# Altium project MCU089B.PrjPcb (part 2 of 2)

## Sheet MCU089B_XDS110_USB_Power.SchDoc
size 431 x 279 mm; Date: Not shown in title block; ApprovedBy: Not shown in title block; CheckedBy: Not shown in title block; Author: Not shown in title block; CompanyName: Not shown in title block; Engineer: Not shown in title block; Organization: Not shown in title block; Address1: Not shown in title block; Address2: Not shown in title block; Address3: Not shown in title block; Address4: Not shown in title block; DocumentNumber: 6; Revision: Use project parameter SCH_Rev; SheetNumber: 6; SheetTotal: 8; PageSetup: Record=PageOptions¦CenterHorizontal=True¦CenterVertical=True¦PrintScale=1.00¦XCorrection=1.00¦YCorrection=1.00¦PrintKind=0¦BorderSize=5000000¦LeftOffset=0¦BottomOffset=0¦Orientation=2¦PaperLength=1000¦PaperWidth=1000¦Scale=100¦PaperSource=15¦PrintQuality=600¦MediaType=1¦DitherType=10¦PaperKind=Letter¦PrintScaleMode=1
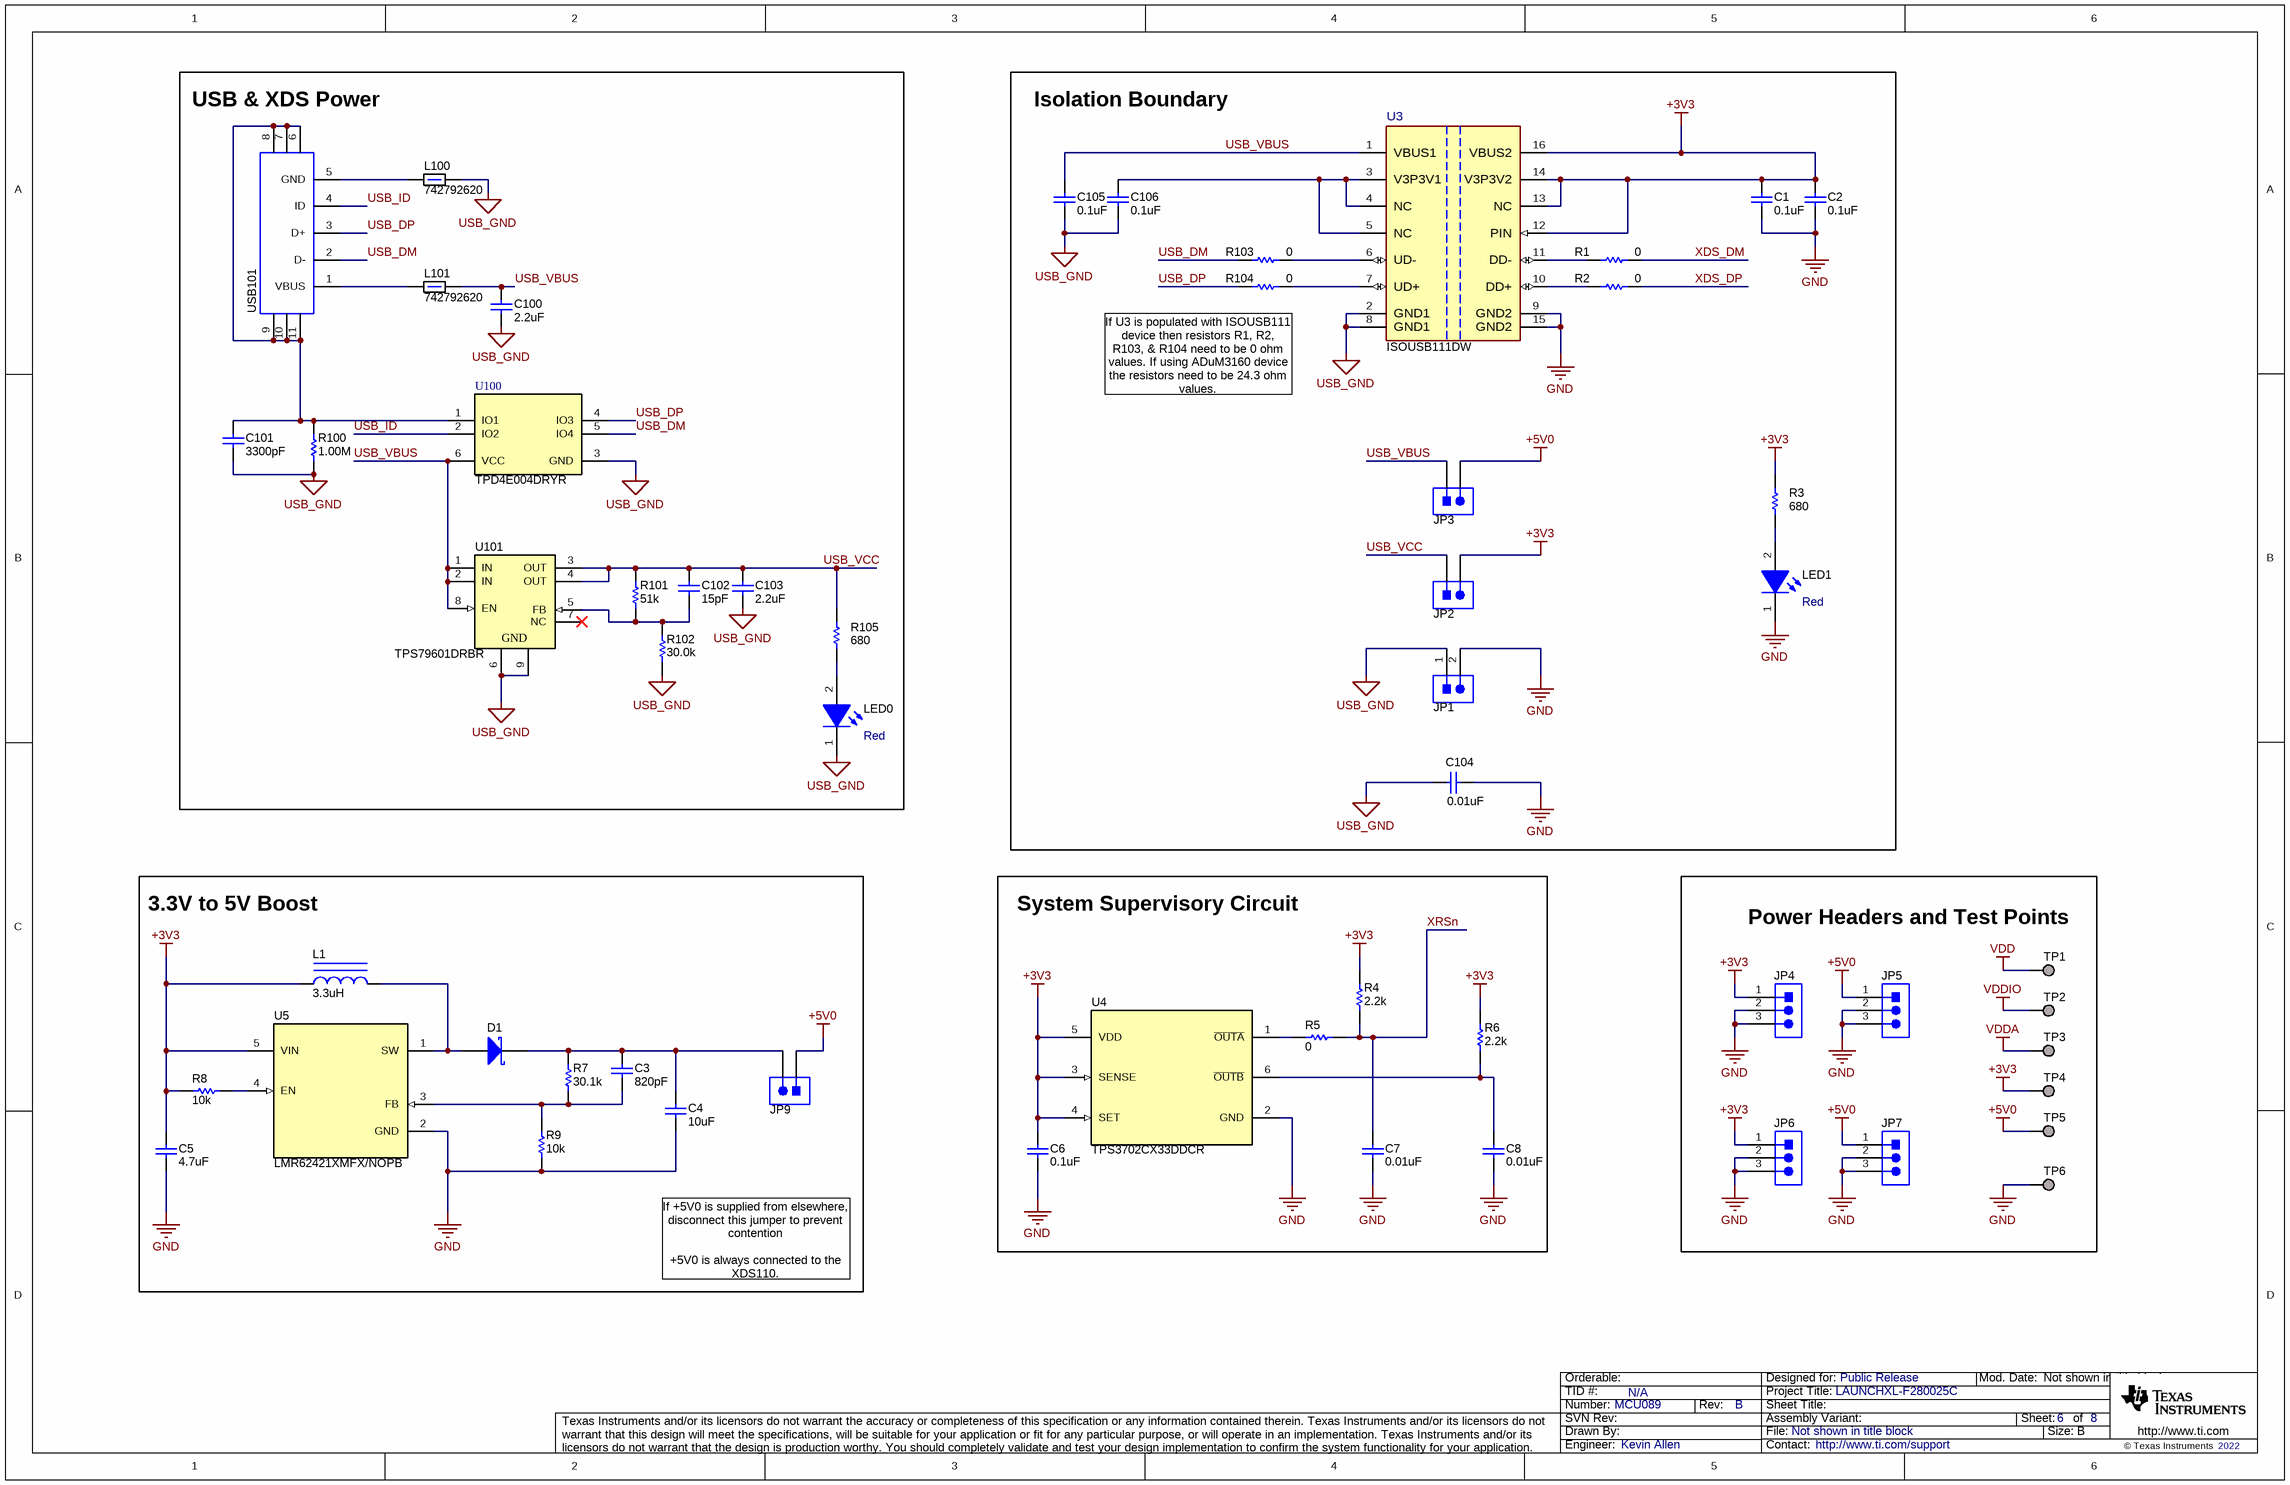
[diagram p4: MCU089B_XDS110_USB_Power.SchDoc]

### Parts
C1  ValueDisplayed: 0.1uF  [0402]  (hidden comment: GRM155R71A104KA01D)
C2  ValueDisplayed: 0.1uF  [0402]  (hidden comment: GRM155R71A104KA01D)
C3  ValueDisplayed: 820pF  [0402]  (hidden comment: GRM1555C1E821JA01D)
C4  ValueDisplayed: 10uF  [1210_220]  (hidden comment: 885012209028)
C5  ValueDisplayed: 4.7uF  [0402]  (hidden comment: 885012105008)
C6  ValueDisplayed: 0.1uF  [0402]  (hidden comment: GRM155R71A104KA01D)
C7  ValueDisplayed: 0.01uF  [0402]  (hidden comment: GRM155R71E103KA01D)
C8  ValueDisplayed: 0.01uF  [0402]  (hidden comment: GRM155R71E103KA01D)
C100  ValueDisplayed: 2.2uF  [0402]  (hidden comment: GRM155R60J225KE95D)
C101  ValueDisplayed: 3300pF  [0402]  (hidden comment: GRM155R71H332KA01D)
C102  ValueDisplayed: 15pF  [0402]  (hidden comment: 885012005056)
C103  ValueDisplayed: 2.2uF  [0402]  (hidden comment: GRM155R60J225KE95D)
C104  ValueDisplayed: 0.01uF  [1812]  (hidden comment: 1812SC103KAT1A)
C105  ValueDisplayed: 0.1uF  [0402]  (hidden comment: GRM155R71A104KA01D)
C106  ValueDisplayed: 0.1uF  [0402]  (hidden comment: GRM155R71A104KA01D)
D1  1N5819HW-7-F  [SOD-123]  (value not drawn)
JP1  61300211121  [WURTH_61300211121]  (value not drawn)
JP2  61300211121  [WURTH_61300211121]  (value not drawn)
JP3  61300211121  [WURTH_61300211121]  (value not drawn)
JP4  61300311121  [WURTH_61300311121]  (value not drawn)
JP5  61300311121  [WURTH_61300311121]  (value not drawn)
JP6  61300311121  [WURTH_61300311121]  (value not drawn)
JP7  61300311121  [WURTH_61300311121]  (value not drawn)
JP9  61300211121  [WURTH_61300211121]  (value not drawn)
L1  ValueDisplayed: 3.3uH  [WE-TPC_2828]  (hidden comment: 744025003)
L100  742792620  [0603]
L101  742792620  [0603]
LED0  value Red  [WL-SMCW_RED_0805]  (hidden comment: 150080SS75000)
LED1  value Red  [WL-SMCW_RED_0805]  (hidden comment: 150080SS75000)
R1  ValueDisplayed: 0  [0402]  (hidden comment: RC0402JR-070RL)
R2  ValueDisplayed: 0  [0402]  (hidden comment: RC0402JR-070RL)
R3  ValueDisplayed: 680  [0402]  (hidden comment: CRCW0402680RJNED)
R4  ValueDisplayed: 2.2k  [0402]  (hidden comment: CRCW04022K20JNED)
R5  ValueDisplayed: 0  [0402]  (hidden comment: CRCW04020000Z0ED)
R6  ValueDisplayed: 2.2k  [0603]  (hidden comment: CRCW06032K20JNEA)
R7  ValueDisplayed: 30.1k  [0402]  (hidden comment: RC0402FR-0730K1L)
R8  ValueDisplayed: 10k  [0402]  (hidden comment: CRCW040210K0JNED)
R9  ValueDisplayed: 10k  [0402]  (hidden comment: CRCW040210K0JNED)
R100  ValueDisplayed: 1.00M  [0402]  (hidden comment: CRCW04021M00FKED)
R101  ValueDisplayed: 51k  [0402]  (hidden comment: CRCW040251K0FKED)
R102  ValueDisplayed: 30.0k  [0402]  (hidden comment: CRCW040230K0FKED)
R103  ValueDisplayed: 0  [0402]  (hidden comment: RC0402JR-070RL)
R104  ValueDisplayed: 0  [0402]  (hidden comment: RC0402JR-070RL)
R105  ValueDisplayed: 680  [0402]  (hidden comment: CRCW0402680RJNED)
TP1  TESTPOINT  [TP_50MIL-25MILHOLE]  (value not drawn)  (no BOM)
TP2  TESTPOINT  [TP_50MIL-25MILHOLE]  (value not drawn)  (no BOM)
TP3  TESTPOINT  [TP_50MIL-25MILHOLE]  (value not drawn)  (no BOM)
TP4  TESTPOINT  [TP_50MIL-25MILHOLE]  (value not drawn)  (no BOM)
TP5  TESTPOINT  [TP_50MIL-25MILHOLE]  (value not drawn)  (no BOM)
TP6  TESTPOINT  [TP_50MIL-25MILHOLE]  (value not drawn)  (no BOM)
U3  ISOUSB111DW  [DW0016B-MFG]
U4  TPS3702CX33DDCR  [DDC0006A_N]
U5  LMR62421XMFX/NOPB  [DBV0005A_N]
U100  TPD4E004DRYR  [DRY0006A]
U101  TPS79601DRBR  [DRB0008B]
USB101  1051640001  [Molex_1051640001]  (value not drawn)

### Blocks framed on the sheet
USB & XDS Power: C100-C103 L100 L101 LED0 R100-R102 R105 U100 U101 USB101
Isolation Boundary: C1 C2 C104-C106 JP1-JP3 LED1 R1-R3 R103 R104 U3
3.3V to 5V Boost: C3-C5 D1 JP9 L1 R7-R9 U5
System Supervisory Circuit: C6-C8 R4-R6 U4
Power Headers and Test Points: JP4-JP7 TP1-TP6

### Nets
+3V3: C1.2 C2.2 C5.1 C6.2 JP2.2 JP4.1 JP6.1 L1.1 R3.2 R4.2 R6.2 R8.2 TP4.1 U3.12(PIN) U3.13(NC) U3.14(V3P3V2) U3.16(VBUS2) U4.3(SENSE) U4.4(SET) U4.5(VDD) U5.5(VIN)
+5V0: JP3.2 JP5.1 JP7.1 JP9.1 TP5.1
GND: C1.1 C2.1 C4.2 C5.2 C6.1 C7.2 C8.2 C104.1 JP1.2 JP4.2 JP4.3 JP5.2 JP5.3 JP6.2 JP6.3 JP7.2 JP7.3 LED1.1(K) R9.1 TP6.1 U3.9(GND2) U3.15(GND2) U4.2(GND) U5.2(GND)
USB_GND: C100.2 C101.2 C103.2 C104.2 C105.1 C106.1 JP1.1 L100.2 LED0.1(K) R100.1 R102.1 U3.2(GND1) U3.8(GND1) U100.3(GND) U101.6(GND) U101.9(GND)
VDD: TP1.1
VDDA: TP3.1
VDDIO: TP2.1
USB_DM: R103.1 U100.5(IO4) USB101.2(D-)
USB_DP: R104.1 U100.4(IO3) USB101.3(D+)
USB_ID: U100.2(IO2) USB101.4(ID)
USB_VBUS: C100.1 C105.2 JP3.1 L101.2 U3.1(VBUS1) U100.6(VCC) U101.1(IN) U101.2(IN) U101.8(EN)
USB_VCC: C102.1 C103.1 JP2.1 R101.2 R105.2 U101.3(OUT) U101.4(OUT)
XDS_DM: R1.2
XDS_DP: R2.2
XRSn: C7.1 R4.1 R5.2
NetC3_1: C3.1 C4.1 D1.1(K) JP9.2 R7.2
NetC3_2: C3.2 R7.1 R9.2 U5.3(FB)
NetC8_1: C8.1 R6.1 U4.6(~{OUTB})
NetC101_1: C101.1 R100.2 U100.1(IO1) USB101.6 USB101.7 USB101.8 USB101.9 USB101.10 USB101.11
NetC102_2: C102.2 R101.1 R102.2 U101.5(FB)
NetC106_2: C106.2 U3.3(V3P3V1) U3.4(NC) U3.5(NC)
NetD1_2: D1.2(A) L1.2 U5.1(SW)
NetL100_1: L100.1 USB101.5(GND)
NetL101_1: L101.1 USB101.1(VBUS)
NetLED0_2: LED0.2(A) R105.1
NetLED1_2: LED1.2(A) R3.1
NetR1_1: R1.1 U3.11(DD-)
NetR2_1: R2.1 U3.10(DD+)
NetR5_1: R5.1 U4.1(~{OUTA})
NetR8_1: R8.1 U5.4(EN)
NetR103_2: R103.2 U3.6(UD-)
NetR104_2: R104.2 U3.7(UD+)

Not connected (* = marked no-connect by the designer): U101 7(NC)*

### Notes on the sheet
- (near R104) If U3 is populated with ISOUSB111 device then resistors R1, R2, R103, & R104 need to be 0 ohm values. If using ADuM3160 device the resistors need to be 24.3 ohm values.
- If +5V0 is supplied from elsewhere, disconnect this jumper to prevent contention
  +5V0 is always connected to the XDS110.

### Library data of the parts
C1 C2 C6 C105 C106 = CMP-0006629-2: CAP, CERM, 0.1 uF, 10 V, +/- 10%, X7R, 0402; Manufacturer: MuRata; Polarized: N; Value: 0.1uF; U/M: EA; Cap_F: 100nF; Value1: Unknown; VDC_V: 10V; TaMin_C: -55°C; TaMax_C: 125°C; SizeArea_mm2: 0.5; SizeAreaWB_mm2: 3; SizeX_mm: 1; SizeZ_mm: 0.6; AEC Category: Q200
C3 = CMP-0006404-2: CAP, CERM, 820 pF, 25 V, +/- 5%, C0G/NP0, 0402; Manufacturer: MuRata; TaMin_C: -55°C; Polarized: N; SizeAreaWB_mm2: 3; Value1: Unknown; U/M: EA; Value: 820pF; TaMax_C: 125°C; SizeZ_mm: 0.6; SizeX_mm: 1; SizeY_mm: 0.5; Value2: 25V; AEC Category: Q200
C4 = CMP-0064938-2: CAP, CERM, 10 uF, 25 V,+/- 10%, X7R, 1210; Manufacturer: Wurth Elektronik; Polarized: N; Value: 10uF; U/M: EA; Cap_F: 10µF; Value1: Unknown; VDC_V: 25V; TaMin_C: -55°C; TaMax_C: 125°C; Cap_Case: 1210; SizeArea_mm2: 8; SizeAreaWB_mm2: 14.7; SizeX_mm: 3.2; SizeY_mm: 2.5; SizeZ_mm: 2.2; AEC Category: Q200
C5 = CMP-0006220-2: CAP, CERM, 4.7 uF, 6.3 V, +/- 20%, X5R, 0402; Manufacturer: Wurth Elektronik; Polarized: N; Value: 4.7uF; U/M: EA; Cap_F: 4.7µF; Value1: Unknown; VDC_V: 6.3V; TaMin_C: -55°C; TaMax_C: 85°C; SizeArea_mm2: 0.5; SizeAreaWB_mm2: 3; SizeX_mm: 1; SizeZ_mm: 0.6; AEC Category: Q200
C7 C8 = CMP-0006658-2: CAP, CERM, 0.01 uF, 25 V, +/- 10%, X7R, 0402; Manufacturer: MuRata; Polarized: N; Value: 0.01uF; U/M: EA; Cap_F: 10nF; Value1: Unknown; VDC_V: 25V; TaMin_C: -55°C; TaMax_C: 125°C; SizeArea_mm2: 0.5; SizeAreaWB_mm2: 3; SizeX_mm: 1; SizeZ_mm: 0.6; AEC Category: Q200
C100 C103 = CMP-0006543-2: CAP, CERM, 2.2 uF, 6.3 V, +/- 10%, X5R, 0402; Manufacturer: MuRata; Polarized: N; Value: 2.2uF; U/M: EA; Cap_F: 2.2µF; Value1: Unknown; VDC_V: 6.3V; TaMin_C: -55°C; TaMax_C: 85°C; SizeArea_mm2: 0.5; SizeAreaWB_mm2: 3; SizeX_mm: 1; SizeZ_mm: 0.6; AEC Category: Q200
C101 = CMP-0006688-2: CAP, CERM, 3300 pF, 50 V, +/- 10%, X7R, 0402; Manufacturer: MuRata; Polarized: N; Value: 3300pF; U/M: EA; Cap_F: 3.3nF; Value1: Unknown; VDC_V: 50V; TaMin_C: -55°C; TaMax_C: 125°C; SizeArea_mm2: 0.5; SizeAreaWB_mm2: 3; SizeX_mm: 1; SizeZ_mm: 0.6; AEC Category: Q200
C102 = CMP-0006216-2: CAP, CERM, 15 pF, 50 V, +/- 5%, C0G/NP0, 0402; Manufacturer: Wurth Elektronik; Polarized: N; Value: 15pF; U/M: EA; Value1: Unknown; VDC_V: 50V; TaMin_C: -55°C; TaMax_C: 125°C; SizeArea_mm2: 0.5; SizeAreaWB_mm2: 3; SizeX_mm: 1; SizeZ_mm: 0.6; AEC Category: Q200
C104 = CMP-0009297-2: CAP, CERM, 0.01 uF, 1500 V, +/- 10%, X7R, 1812; Manufacturer: AVX; TaMin_C: -55°C; ESR_ohm: 0.05; Polarized: N; SizeAreaWB_mm2: 23.1; Value1: 0.05 ohm; U/M: EA; Value: 0.01uF; TaMax_C: 125°C; SizeZ_mm: 1.35; SizeX_mm: 4.5; SizeY_mm: 3.2; Value2: 1500V; SizeArea_mm2: 14.4; Cap_F: 10nF; VDC_V: 1.5kV; AEC Category: Q200
D1 = CMP-0028360-2: Diode, Schottky, 40 V, 1 A, SOD-123; Manufacturer: Diodes Inc.; Vf_V: 450mV; Value: 40V; Value1: 1A; Value2: 0.45V; TJmax_C: 125°C; SizeAreaWB_mm2: 13.095; SizeArea_mm2: 6.545; SizeX_mm: 3.85; SizeY_mm: 1.7; SizeZ_mm: 1.35; AEC Category: Q101; Green_Lifecycle: Active; Green_REACh: Passed
JP1-JP3 JP9 = CMP-0054794-1: Header, 2.54 mm, 2x1, Gold, TH; Manufacturer: Wurth Elektronik; Green_Lifecycle: Active; Green_REACh: Passed; CNHeader: TRUE; CT: FALSE
JP4-JP7 = CMP-0054796-1: Header, 2.54 mm, 3x1, Gold, TH; Manufacturer: Wurth Elektronik; Green_Lifecycle: Active; Green_REACh: Passed; CNHeader: TRUE; CT: FALSE
L1 = CMP-0063754-1: Inductor, Shielded Drum Core, Ferrite, 3.3 uH, 1.5 A, 0.085 ohm, SMD; Manufacturer: Wurth Elektronik; Value: 3.3uH; Ind_H: 3.3µH; Imax_A: 1.5A; Irms: 1.5A @ 40C rise; Isat: 1.8A @ 35% inductance drop; DCR_ohm: 0.085; SizeAreaWB_mm2: 14.44; SizeArea_mm2: 7.84; SizeX_mm: 2.8; SizeZ_mm: 3; AEC Category: Q200; Green_Lifecycle: Active; Green_REACh: Passed
L100 L101 = CMP-0003183-2: Ferrite Bead, 100 ohm @ 100 MHz, 0.5 A, 0603; Manufacturer: Wurth Elektronik; Ztyp@1GHz_Ohm: 137.267; ZTyp@100MHz_Ohm: 100; SizeAreaWB_mm2: 4.68; DCR_ohm: 1.5d; Value1: 0.15 ohm; Value: 100 ohm; Imax_A: 5dA; SizeZ_mm: 1; SizeX_mm: 1.6; SizeY_mm: 0.8; Value2: 0.5A; SizeArea_mm2: 1.28
LED0 LED1 = CMP-0002951-3: LED, Red, SMD; Manufacturer: Wurth Elektronik; Type: AlInGaP; Vf_V: 1.9V; Io_A: 30mA; Vr_V: 5V; Ir_A: 25µA; Tjmax_C: 85°C; Power_TotalModule: 72mW; Value1: 0.072W; Angle: 140
R1 R2 R103 R104 = CMP-0027004-2: RES, 0, 5%, 0.063 W, 0402; Manufacturer: Yageo America; Power_W: 63mW; TempCo: 200 ppm/C; Value_Code: 0000; U/M: EA; Value: 0; EIA_Code: E24; SizeX_mm: 1; SizeY_mm: 0.5; SizeZ_mm: 0.6; Value2: 0.063W; VDC_V: 50V; AEC Category: Q200
R3 R105 = CMP-0026962-3: RES, 680, 5%, 0.063 W, AEC-Q200 Grade 0, 0402; Manufacturer: Vishay-Dale; Power_W: 63mW; TempCo: 200 ppm/C; Value_Code: 680R; Value: 680; EIA_Code: E24; SizeX_mm: 1; SizeY_mm: 0.5; SizeZ_mm: 0.6; Value2: 0.063W; CompType: Resistor; AEC Qualified: Y; VDC_V: 50V; AEC Category: Q200; AEC Grade: 0
R4 = CMP-0026890-5: RES, 2.2 k, 5%, 0.063 W, AEC-Q200 Grade 0, 0402; Manufacturer: Vishay-Dale; Value: 2.2k; Value_Code: 2k20; Power_W: 63mW; Value2: 0.063W; VDC_V: 50V; TempCo: 200 ppm/C; SizeArea_mm2: 0.5; SizeX_mm: 1; SizeZ_mm: 0.6; EIA_Code: E24; AEC Category: Q200; AEC Qualified: Y; AEC Grade: 0
R5 = CMP-0026822-3: RES, 0, 5%, 0.063 W, AEC-Q200 Grade 0, 0402; Manufacturer: Vishay-Dale; Value: 0; Value_Code: 0000; Power_W: 63mW; Value2: 0.063W; VDC_V: 50V; TempCo: 200 ppm/C; SizeArea_mm2: 0.5; SizeX_mm: 1; SizeZ_mm: 0.6; EIA_Code: E24; AEC Category: Q200; AEC Qualified: Y
R6 = CMP-0025769-4: RES, 2.2 k, 5%, 0.1 W, AEC-Q200 Grade 0, 0603; Manufacturer: Vishay-Dale; Value: 2.2k; Value_Code: 2k20; Power_W: 100mW; Value2: 0.1W; VDC_V: 75V; TempCo: 200 ppm/C; SizeArea_mm2: 1.28; SizeX_mm: 1.6; SizeY_mm: 0.8; SizeZ_mm: 1; EIA_Code: E24; AEC Category: Q200; AEC Qualified: Y; AEC Grade: 0
R7 = CMP-0026730-1: RES, 30.1 k, 1%, 0.063 W, 0402; Manufacturer: Yageo America; Value: 30.1k; Value_Code: 30k1; Power_W: 63mW; Value2: 0.063W; VDC_V: 50V; TempCo: 100 ppm/C; SizeArea_mm2: 0.5; SizeX_mm: 1; SizeZ_mm: 0.6; EIA_Code: E96; U/M: EA; AEC Category: Q200; AEC Qualified: N
R8 R9 = CMP-0026825-5: RES, 10 k, 5%, 0.063 W, AEC-Q200 Grade 0, 0402; Manufacturer: Vishay-Dale; Value: 10k; Value_Code: 10k0; Power_W: 63mW; Value2: 0.063W; VDC_V: 50V; TempCo: 200 ppm/C; SizeArea_mm2: 0.5; SizeX_mm: 1; SizeZ_mm: 0.6; EIA_Code: E24; AEC Category: Q200; AEC Qualified: Y; AEC Grade: 0
R100 = CMP-0026100-2: RES, 1.00 M, 1%, 0.063 W, AEC-Q200 Grade 0, 0402; Manufacturer: Vishay-Dale; Value: 1.00Meg; Res_ohm: 1M; Value_Code: 1M00; Power_W: 63mW; Value2: 0.063W; VDC_V: 50V; TempCo: 100 ppm/C; SizeArea_mm2: 0.5; SizeX_mm: 1; SizeZ_mm: 0.6; EIA_Code: E96; AEC Category: Q200; AEC Qualified: Y; AEC Grade: 0
R101 = CMP-0088102-2: RES Thick Film SMD 51kΩ 1% 1/16W 0402 100ppm/K; Manufacturer: Vishay; SizeX_mm: 1; Power_W: 63mW; AEC Qualified: Yes; VDC_V: 50V; SizeZ_mm: 0.6; SizeY_mm: 0.5; AEC Grade: Grade 0
R102 = CMP-0078244-2: RES, 30.0 k, 1%, 0.063 W, AEC-Q200 Grade 0, 0402; Manufacturer: Vishay-Dale; Power_W: 63mW; Green_Lifecycle: Active; TempCo: 100 ppm/C; Value_Code: 30k0; Green_REACh: Passed; Value: 30.0k; Res_ohm: 30k; SizeX_mm: 1; SizeY_mm: 0.5; SizeZ_mm: 0.6; Value2: 0.063W; AEC Qualified: Y; VDC_V: 50V; AEC Grade: 0; AEC Category: Q200
TP1-TP6 = CMP-0078143-3: TEST POINT.  No entry in BOM.
U3 = CMP-0091303-1: Full/Low Speed Isolated USB Repeater, SOIC16-Wide; Manufacturer: Texas Instruments; Number Of Ports: 1; Usb Standard: USB 2.0; Min Supply Voltage: 3V; Data Rate: 12Mbits/s; Max Supply Voltage: 5.5V; TaMin_C: -40°C; SizeZ_mm: 2.65mm; TaMax_C: +125°C; Nominal Supply Current: 9-9.5mA; TJmax_C: +150°C; Standoff Height: 0.1mm; AEC Qualified: No
U4 = CMP-0067340-2: High-Accuracy, Fixed-Threshold OV/UV Monitor, DDC0006A (SOT-23-T-6); Alternate PartNumber: TPS3702CX33DDCT; Manufacturer: Texas Instruments; SizeArea_mm2: 4.8675; SizeAreaWB_mm2: 10.4675; SizeX_mm: 1.65; SizeY_mm: 2.95; SizeZ_mm: 0.87; CompType: IC; U/M: EA
U5 = CMP-0066119-1: SIMPLE SWITCHER 2.7V to 5.5V, 2.1A Step-Up Regulator in SOT-23, DBV0005A (SOT-23-5); Alternate PartNumber: LMR62421XMFE/NOPB; Manufacturer: Texas Instruments; SizeArea_mm2: 8.12; SizeAreaWB_mm2: 14.82; SizeX_mm: 2.8; SizeY_mm: 2.9; SizeZ_mm: 1.45; CompType: IC; U/M: EA; Green_Lifecycle: Active; Green_REACh: Passed
U100 = CMP-0043115-3: 4-Channel ESD Protection Array for High-Speed Data Interfaces, DRY0006A (USON-6); Manufacturer: Texas Instruments; 1394 / Firewire: TRUE; Breakdown Voltage(Min)(V): 6; Eco-Plan: Green (RoHS & no Sb/Br); IEC 61000-4-2 Air-Gap(+/- kV): 12; IEC 61000-4-2 Contact(+/- kV): 8; IO Capacitance(Typ)(pF): 1.6; IO Leakage Current(nA): 1; AEC Category: Q200; AEC Qualified: N; CompType: IC; SizeArea_mm2: 1.45; SizeAreaWB_mm2: 4.9; SizeX_mm: 1.0; SizeZ_mm: 0.6; Rating: Catalog
U101 = CMP-0036402-3: Single Output High PSRR LDO, 1 A, Adjustable 1.2 to 5.5 V Output, 2.7 to 5.5 V Input, 8-pin SON (DRB), -40 to 125 degC, Green (RoHS & no Sb/Br); Manufacturer: Texas Instruments; Accuracy(%): 2; Iout(Max)(A): 1; Iq(Typ)(mA): 0.26; SubFamily: Single Channel LDO; Vdo(Typ)(mV): 250; Vin(Max)(V): 5.5; Vin(Min)(V): 2.7; Vout Adj(Min)(V): 1.2; AEC Category: Q200; AEC Qualified: N; CompType: IC; SizeAreaWB_mm2: 16.0; SizeArea_mm2: 9.0; SizeX_mm: 3.0; SizeZ_mm: 1.0
USB101 = CMP-0055311-1: Receptacle, USB 2.0, Micro B, 5 Position, R/A, SMT; Manufacturer: Molex; Pitch_mm: 0.65; Gender: Female; ContactFinish: Gold; Current_A: 1.8A; Voltage_V: 30V; Cert_UL: Y; CNHeader: FALSE; CT: TRUE

## Sheet MCU089B_XDS110_MCU.SchDoc
size 431 x 279 mm; Date: Not shown in title block; ApprovedBy: Not shown in title block; CheckedBy: Not shown in title block; Author: Not shown in title block; CompanyName: Not shown in title block; Engineer: Not shown in title block; Organization: Not shown in title block; Address1: Not shown in title block; Address2: Not shown in title block; Address3: Not shown in title block; Address4: Not shown in title block; DocumentNumber: 7; Revision: Use project parameter SCH_Rev; SheetNumber: 7; SheetTotal: 8; PageSetup: Record=PageOptions¦CenterHorizontal=True¦CenterVertical=True¦PrintScale=1.00¦XCorrection=1.00¦YCorrection=1.00¦PrintKind=0¦BorderSize=5000000¦LeftOffset=0¦BottomOffset=0¦Orientation=2¦PaperLength=1000¦PaperWidth=1000¦Scale=100¦PaperSource=15¦PrintQuality=600¦MediaType=1¦DitherType=10¦PaperKind=Letter¦PrintScaleMode=1
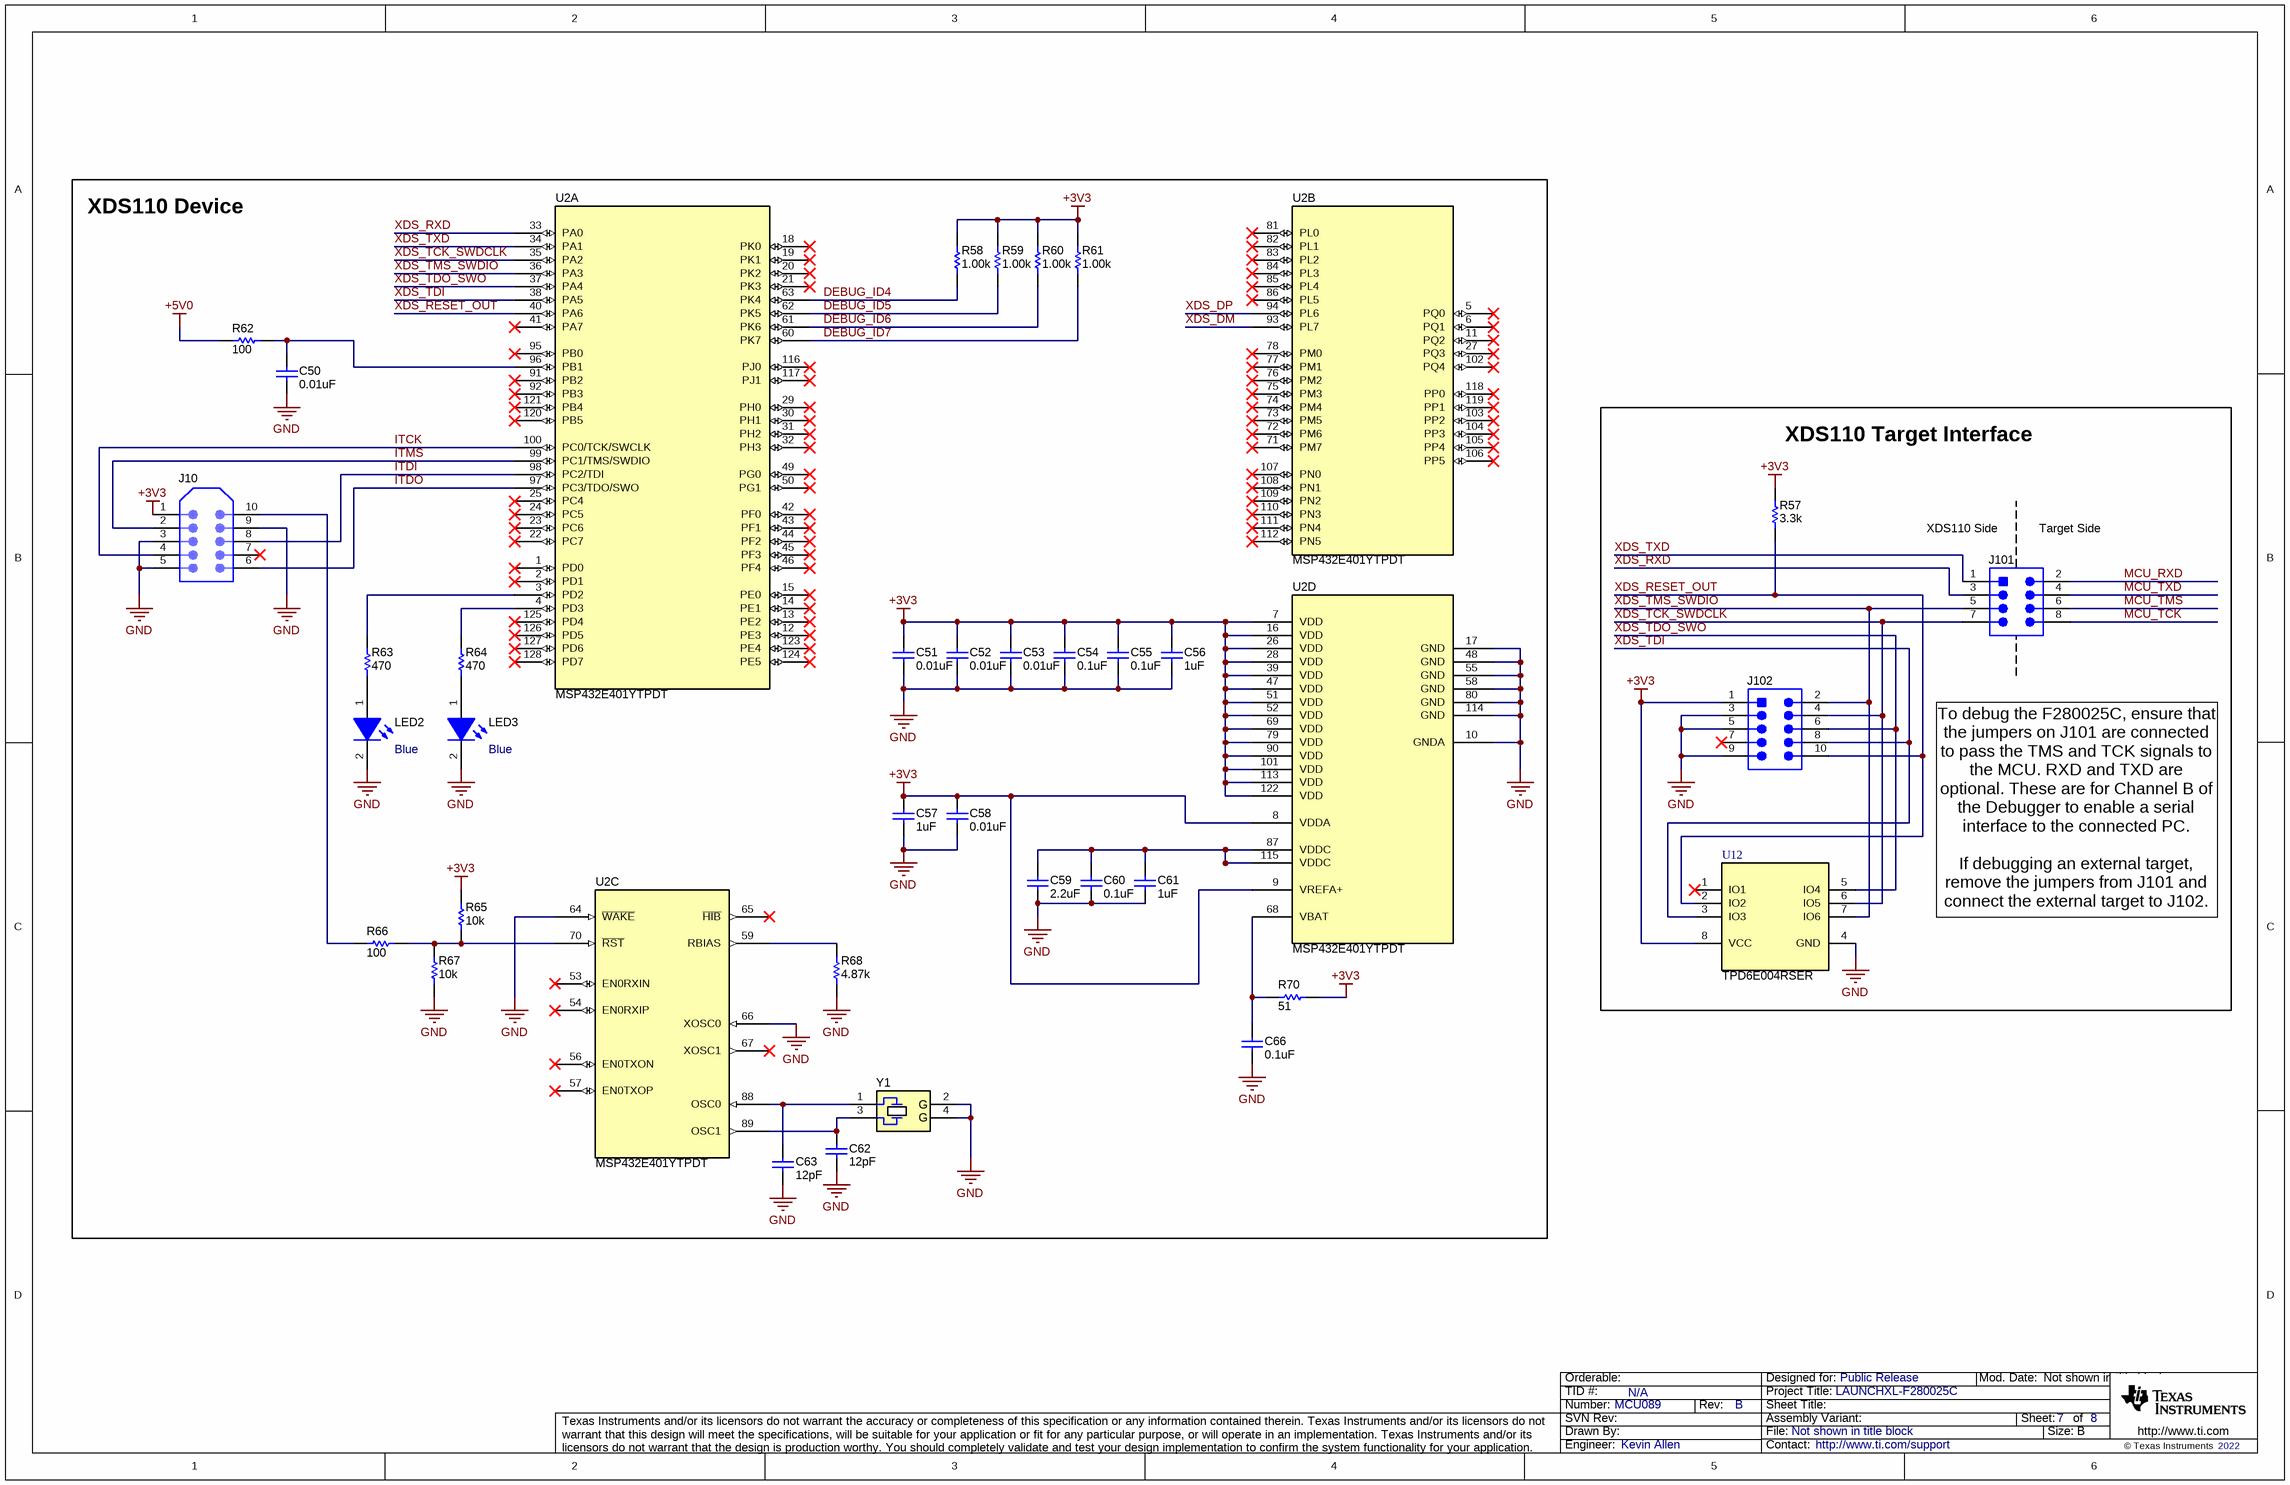
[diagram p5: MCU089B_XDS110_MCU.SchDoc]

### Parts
C50  ValueDisplayed: 0.01uF  [0402]  (hidden comment: GRM155R71E103KA01D)
C51  ValueDisplayed: 0.01uF  [0402]  (hidden comment: GRM155R71E103KA01D)
C52  ValueDisplayed: 0.01uF  [0402]  (hidden comment: GRM155R71E103KA01D)
C53  ValueDisplayed: 0.01uF  [0402]  (hidden comment: GRM155R71E103KA01D)
C54  ValueDisplayed: 0.1uF  [0402]  (hidden comment: GRM155R70J104KA01D)
C55  ValueDisplayed: 0.1uF  [0402]  (hidden comment: GRM155R70J104KA01D)
C56  ValueDisplayed: 1uF  [0402]  (hidden comment: 885012105012)
C57  ValueDisplayed: 1uF  [0402]  (hidden comment: 885012105012)
C58  ValueDisplayed: 0.01uF  [0402]  (hidden comment: GRM155R71E103KA01D)
C59  ValueDisplayed: 2.2uF  [0402]  (hidden comment: GRM155R60J225KE95D)
C60  ValueDisplayed: 0.1uF  [0402]  (hidden comment: GRM155R70J104KA01D)
C61  ValueDisplayed: 1uF  [0402]  (hidden comment: 885012105012)
C62  ValueDisplayed: 12pF  [0402]  (hidden comment: C0402C120J3GACAUTO)
C63  ValueDisplayed: 12pF  [0402]  (hidden comment: C0402C120J3GACAUTO)
C66  ValueDisplayed: 0.1uF  [0402]  (hidden comment: GRM155R70J104KA01D)
J10  TC2050-IDC-NL-FP  [Tag_TC2050-NL]  (value not drawn)  (no BOM)
J101  TSW-104-07-G-D  [TSW-104-07-G-D]  (value not drawn)
J102  FTSH-105-01-F-DV-K  [Samtec_FTSH-105-01-x-DV-K]  (value not drawn)
LED2  value Blue  [LTST-C170TBKT_Blue]  (hidden comment: LTST-C170TBKT)
LED3  value Blue  [LTST-C170TBKT_Blue]  (hidden comment: LTST-C170TBKT)
R57  ValueDisplayed: 3.3k  [0402]  (hidden comment: CRCW04023K30JNED)
R58  ValueDisplayed: 1.00k  [0402]  (hidden comment: CRCW04021K00FKED)
R59  ValueDisplayed: 1.00k  [0402]  (hidden comment: CRCW04021K00FKED)
R60  ValueDisplayed: 1.00k  [0402]  (hidden comment: CRCW04021K00FKED)
R61  ValueDisplayed: 1.00k  [0402]  (hidden comment: CRCW04021K00FKED)
R62  ValueDisplayed: 100  [0402]  (hidden comment: CRCW0402100RJNED)
R63  ValueDisplayed: 470  [0402]  (hidden comment: ERJ-2RKF4700X)
R64  ValueDisplayed: 470  [0402]  (hidden comment: ERJ-2RKF4700X)
R65  ValueDisplayed: 10k  [0402]  (hidden comment: CRCW040210K0JNED)
R66  ValueDisplayed: 100  [0402]  (hidden comment: CRCW0402100RJNED)
R67  ValueDisplayed: 10k  [0402]  (hidden comment: CRCW040210K0JNED)
R68  ValueDisplayed: 4.87k  [0402]  (hidden comment: CRCW04024K87FKED)
R70  ValueDisplayed: 51  [0402]  (hidden comment: CRCW040251R0JNED)
U2  MSP432E401YTPDT  [PDT0128A]  (parts A,B,C,D of 4)
U12  TPD6E004RSER  [RSE0008A]
Y1  NX3225GA-16.000M-STD-CRG-1  [NDK_NX3225GA]  (value not drawn)

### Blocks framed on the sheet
XDS110 Device: C50-C63 C66 J10 LED2 LED3 R58-R68 R70 U2 Y1
XDS110 Target Interface: J101 J102 R57 U12

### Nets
+3V3: C51.1 C52.1 C53.1 C54.1 C55.1 C56.1 C57.1 C58.1 J10.1 J102.1 R57.2 R58.2 R59.2 R60.2 R61.2 R65.2 R70.2 U2.7(VDD) U2.8(VDDA) U2.9(VREFA+) U2.16(VDD) U2.26(VDD) U2.28(VDD) U2.39(VDD) U2.47(VDD) U2.51(VDD) U2.52(VDD) U2.69(VDD) U2.79(VDD) U2.90(VDD) U2.101(VDD) U2.113(VDD) U2.122(VDD) U12.8(VCC)
+5V0: R62.1
GND: C50.2 C51.2 C52.2 C53.2 C54.2 C55.2 C56.2 C57.2 C58.2 C59.2 C60.2 C61.2 C62.2 C63.2 C66.2 J10.3 J10.5 J10.9 J102.3 J102.5 J102.9 LED2.2(K) LED3.2(K) R67.1 R68.1 U2.10(GNDA) U2.17(GND) U2.48(GND) U2.55(GND) U2.58(GND) U2.64(~{WAKE}) U2.66(XOSC0) U2.80(GND) U2.114(GND) U12.4(GND) Y1.2(GND) Y1.4(GND)
DEBUG_ID4: R58.1 U2.63(PK4)
DEBUG_ID5: R59.1 U2.62(PK5)
DEBUG_ID6: R60.1 U2.61(PK6)
DEBUG_ID7: R61.1 U2.60(PK7)
ITCK: J10.4 U2.100(PC0/TCK/SWCLK)
ITDI: J10.8 U2.98(PC2/TDI)
ITDO: J10.6 U2.97(PC3/TDO/SWO)
ITMS: J10.2 U2.99(PC1/TMS/SWDIO)
MCU_RXD: J101.2
MCU_TCK: J101.8
MCU_TMS: J101.6
MCU_TXD: J101.4
XDS_DM: U2.93(PL7)
XDS_DP: U2.94(PL6)
XDS_RESET_OUT: J102.10 R57.1 U2.40(PA6) U12.2(IO2)
XDS_RXD: J101.3 U2.33(PA0)
XDS_TCK_SWDCLK: J101.7 J102.4 U2.35(PA2) U12.6(IO5)
XDS_TDI: J102.8 U2.38(PA5) U12.3(IO3)
XDS_TDO_SWO: J102.6 U2.37(PA4) U12.5(IO4)
XDS_TMS_SWDIO: J101.5 J102.2 U2.36(PA3) U12.7(IO6)
XDS_TXD: J101.1 U2.34(PA1)
NetC50_1: C50.1 R62.2 U2.96(PB1)
NetC59_1: C59.1 C60.1 C61.1 U2.87(VDDC) U2.115(VDDC)
NetC62_1: C62.1 U2.89(OSC1) Y1.3
NetC63_1: C63.1 U2.88(OSC0) Y1.1
NetC66_1: C66.1 R70.1 U2.68(VBAT)
NetJ10_10: J10.10 R66.1
NetLED2_1: LED2.1(A) R63.1
NetLED3_1: LED3.1(A) R64.1
NetR63_2: R63.2 U2.3(PD2)
NetR64_2: R64.2 U2.4(PD3)
NetR65_1: R65.1 R66.2 R67.2 U2.70(~{RST})
NetR68_2: R68.2 U2.59(RBIAS)

Not connected (* = marked no-connect by the designer): J10 7*; J102 7*; U2 1(PD0)* 2(PD1)* 5(PQ0)* 6(PQ1)* 11(PQ2)* 12(PE3)* 13(PE2)* 14(PE1)* 15(PE0)* 18(PK0)* 19(PK1)* 20(PK2)* 21(PK3)* 22(PC7)* 23(PC6)* 24(PC5)* 25(PC4)* 27(PQ3)* 29(PH0)* 30(PH1)* 31(PH2)* 32(PH3)* 41(PA7)* 42(PF0)* 43(PF1)* 44(PF2)* 45(PF3)* 46(PF4)* 49(PG0)* 50(PG1)* 53(EN0RXIN)* 54(EN0RXIP)* 56(EN0TXON)* 57(EN0TXOP)* 65(~{HIB})* 67(XOSC1)* 71(PM7)* 72(PM6)* 73(PM5)* 74(PM4)* 75(PM3)* 76(PM2)* 77(PM1)* 78(PM0)* 81(PL0)* 82(PL1)* 83(PL2)* 84(PL3)* 85(PL4)* 86(PL5)* 91(PB2)* 92(PB3)* 95(PB0)* 102(PQ4)* 103(PP2)* 104(PP3)* 105(PP4)* 106(PP5)* 107(PN0)* 108(PN1)* 109(PN2)* 110(PN3)* 111(PN4)* 112(PN5)* 116(PJ0)* 117(PJ1)* 118(PP0)* 119(PP1)* 120(PB5)* 121(PB4)* 123(PE4)* 124(PE5)* 125(PD4)* 126(PD5)* 127(PD6)* 128(PD7)*; U12 1(IO1)*

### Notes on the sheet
- (near J101) XDS110 Side
- (near J101) Target Side
- To debug the F280025C, ensure that the jumpers on J101 are connected to pass the TMS and TCK signals to the MCU. RXD and TXD are optional. These are for Channel B of the Debugger to enable a serial interface to the connected PC.
  If debugging an external target, remove the jumpers from J101 and connect the external target to J102.

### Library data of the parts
C50-C53 C58 = CMP-0006658-2: as C7 on sheet MCU089B_XDS110_USB_Power
C54 C55 C60 C66 = CMP-0006623-2: CAP, CERM, 0.1 uF, 6.3 V, +/- 10%, X7R, 0402; Manufacturer: MuRata; Polarized: N; Value: 0.1uF; U/M: EA; Cap_F: 100nF; Value1: Unknown; VDC_V: 6.3V; TaMin_C: -55°C; TaMax_C: 125°C; SizeArea_mm2: 0.5; SizeAreaWB_mm2: 3; SizeX_mm: 1; SizeZ_mm: 0.6; AEC Category: Q200
C56 C57 C61 = CMP-0064924-2: CAP, CERM, 1 uF, 10 V,+/- 20%, X5R, 0402; Manufacturer: Wurth Elektronik; Polarized: N; Value: 1uF; U/M: EA; Cap_F: 1µF; Value1: Unknown; VDC_V: 10V; TaMin_C: -55°C; TaMax_C: 85°C; SizeArea_mm2: 0.5; SizeAreaWB_mm2: 3; SizeX_mm: 1; SizeZ_mm: 0.6; AEC Category: Q200
C59 = CMP-0006543-2: as C100 on sheet MCU089B_XDS110_USB_Power
C62 C63 = CMP-0006239-2: CAP, CERM, 12 pF, 25 V, +/- 5%, C0G/NP0, AEC-Q200 Grade 1, 0402; Manufacturer: Kemet; TaMin_C: -55°C; Polarized: N; SizeAreaWB_mm2: 3; Value1: Unknown; U/M: EA; Value: 12pF; TaMax_C: 125°C; SizeZ_mm: 0.6; SizeX_mm: 1; SizeY_mm: 0.5; Value2: 25V; AEC Qualified: Y; AEC Category: Q200
J10 = CMP-0075101-1: Footprint for Tag-Connect TC2050 No-Legs cables; CompType: Receptacle; Note: Footprint only, to mate with Tag-Connect TC2050 No-Legs cables; CNHeader: False
J101 = CMP-0075408-2: Header, 100mil, 4x2, Gold, TH; Manufacturer: Samtec; Pitch_mm: 2.54; Cert_VDE: N; Gender: Male; Cert_CSA: Y; Voltage_V: 550V; Green_REACh: Passed; Current_A: 6.3A; Green_Lifecycle: Active; Row_Count: 2
J102 = CMP-0075670-2: Header (Shrouded), 1.27mm, 5x2, Gold, SMT; Manufacturer: Samtec; Pitch_mm: 1.27; Gender: Male; Shrouded: Y; Row_Count: 2; Current_A: 3.3A
LED2 LED3 = CMP-0002889-2: LED, Blue, SMD; Manufacturer: Lite-On; Type: AlInGaP; Vf_V: 3.3V; Io_A: 20mA; Value1: W
R57 = CMP-0026918-5: RES, 3.3 k, 5%, 0.063 W, AEC-Q200 Grade 0, 0402; Manufacturer: Vishay-Dale; Value: 3.3k; Value_Code: 3k30; Power_W: 63mW; Value2: 0.063W; VDC_V: 50V; TempCo: 200 ppm/C; SizeArea_mm2: 0.5; SizeX_mm: 1; SizeZ_mm: 0.6; EIA_Code: E24; AEC Category: Q200; AEC Qualified: Y; AEC Grade: 0
R58-R61 = CMP-0026071-3: RES, 1.00 k, 1%, 0.063 W, AEC-Q200 Grade 0, 0402; Manufacturer: Vishay-Dale; Power_W: 63mW; TempCo: 100 ppm/C; Value_Code: 1k00; Value: 1.00k; EIA_Code: E96; Res_ohm: 1k; SizeX_mm: 1; SizeY_mm: 0.5; SizeZ_mm: 0.6; Value2: 0.063W; AEC Qualified: Y; VDC_V: 50V; AEC Category: Q200; AEC Grade: 0
R62 R66 = CMP-0026824-3: RES, 100, 5%, 0.063 W, AEC-Q200 Grade 0, 0402; Manufacturer: Vishay-Dale; Value: 100; Value_Code: 100R; Power_W: 63mW; Value2: 0.063W; VDC_V: 50V; TempCo: 200 ppm/C; SizeArea_mm2: 0.5; SizeX_mm: 1; SizeZ_mm: 0.6; EIA_Code: E24; AEC Category: Q200; AEC Qualified: Y; AEC Grade: 0
R63 R64 = CMP-0026699-1: RES, 470, 1%, 0.1 W, AEC-Q200 Grade 0, 0402; Manufacturer: Panasonic; Value: 470; Value_Code: 470R; Power_W: 100mW; Value2: 0.1W; VDC_V: 50V; TempCo: 100 ppm/C; SizeArea_mm2: 0.5; SizeX_mm: 1; SizeZ_mm: 0.6; U/M: EA; AEC Category: Q200; AEC Qualified: Y; AEC Grade: 0
R65 R67 = CMP-0026825-5: as R8 on sheet MCU089B_XDS110_USB_Power
R68 = CMP-0026413-2: RES, 4.87 k, 1%, 0.063 W, AEC-Q200 Grade 0, 0402; Manufacturer: Vishay-Dale; Value: 4.87k; Value_Code: 4k87; Power_W: 63mW; Value2: 0.063W; VDC_V: 50V; TempCo: 100 ppm/C; SizeArea_mm2: 0.5; SizeX_mm: 1; SizeZ_mm: 0.6; EIA_Code: E96; AEC Category: Q200; AEC Qualified: Y; AEC Grade: 0
R70 = CMP-0026946-3: RES, 51, 5%, 0.063 W, AEC-Q200 Grade 0, 0402; Manufacturer: Vishay-Dale; Value: 51; Value_Code: 51R0; Power_W: 63mW; Value2: 0.063W; VDC_V: 50V; TempCo: 200 ppm/C; SizeArea_mm2: 0.5; SizeX_mm: 1; SizeZ_mm: 0.6; EIA_Code: E24; AEC Category: Q200; AEC Qualified: Y; AEC Grade: 0
U2 = CMP-0077953-1: MSP432E401YTPDT, PDT0128A (TQFP-128); Alternate PartNumber: MSP432E401YTPDTR; Alternate Manufacturer: Texas Instruments; SizeAreaWB_mm2: 324; SizeZ_mm: 1.2; SizeX_mm: 16; SizeArea_mm2: 256; CompType: IC; AEC Qualified: N; AEC Category: Q200
U12 = CMP-0043125-4: Low-Capacitance 6-Channel +/-15 kV ESD Protection Array for High-Speed Data Interfaces, RSE0008A (UQFN-8); Manufacturer: Texas Instruments; 1394 / Firewire: TRUE; Breakdown Voltage(Min)(V): 6; Eco-Plan: Green (RoHS & no Sb/Br); IEC 61000-4-2 Air-Gap(+/- kV): 12; IEC 61000-4-2 Contact(+/- kV): 8; IO Capacitance(Typ)(pF): 1.6; IO Leakage Current(nA): 1; SubFamily: ESD Solution; AEC Category: Q200; AEC Qualified: N; CompType: IC; SizeAreaWB_mm2: 6.25; SizeArea_mm2: 2.25; SizeX_mm: 1.5; SizeZ_mm: 0.6
Y1 = CMP-0004635-3: Crystal, 16 MHz, 8pF, SMD; Manufacturer: NDK; TaMin_C: -10°C; TaMax_C: 70°C; Frequency Stability: +/-30ppm; Frequency_Fixed: 16MHz

## Sheet MCU089B_Hardware.SchDoc
size 431 x 279 mm; Date: Not shown in title block; ApprovedBy: Not shown in title block; CheckedBy: Not shown in title block; Author: Not shown in title block; CompanyName: Not shown in title block; Engineer: Not shown in title block; Organization: Not shown in title block; Address1: Not shown in title block; Address2: Not shown in title block; Address3: Not shown in title block; Address4: Not shown in title block; DocumentNumber: 8; Revision: Use project parameter SCH_Rev; SheetNumber: 8; SheetTotal: 8; PageSetup: Record=PageOptions¦CenterHorizontal=True¦CenterVertical=True¦PrintScale=1.00¦XCorrection=1.00¦YCorrection=1.00¦PrintKind=0¦BorderSize=5000000¦LeftOffset=0¦BottomOffset=0¦Orientation=2¦PaperLength=1000¦PaperWidth=1000¦Scale=100¦PaperSource=15¦PrintQuality=600¦MediaType=1¦DitherType=10¦PaperKind=Letter¦PrintScaleMode=1
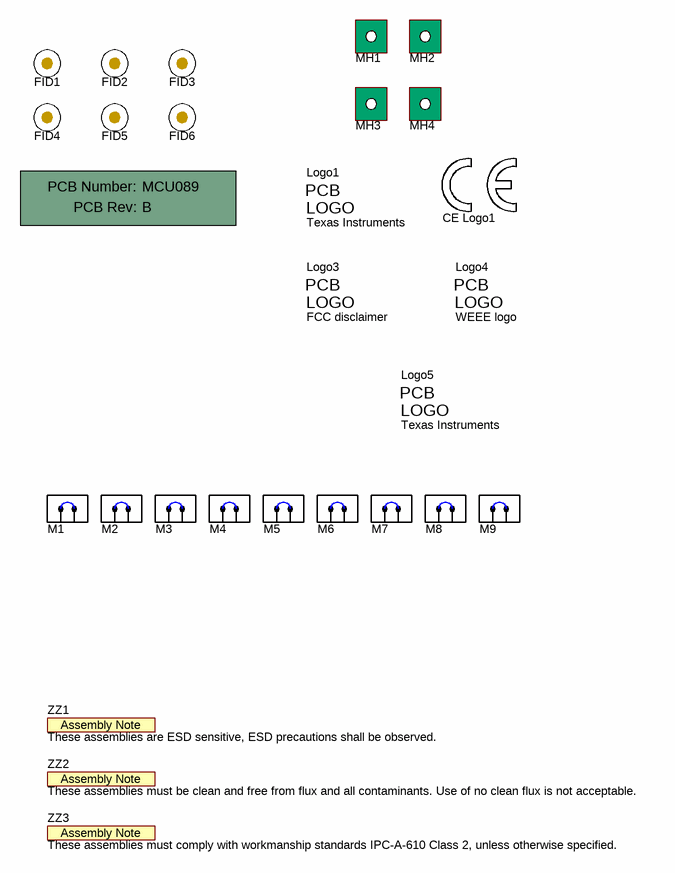
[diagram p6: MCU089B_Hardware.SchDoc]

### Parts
!PCB1  Printed Circuit Board  (value not drawn)  (mechanical)
CE_Logo1  CE Mark  [CE_Mark_5mm]  (value not drawn)  (no BOM)
FID1  Fiducial  [Fiducial10-20]  (value not drawn)  (no BOM)
FID2  Fiducial  [Fiducial10-20]  (value not drawn)  (no BOM)
FID3  Fiducial  [Fiducial10-20]  (value not drawn)  (no BOM)
FID4  Fiducial  [Fiducial10-20]  (value not drawn)  (no BOM)
FID5  Fiducial  [Fiducial10-20]  (value not drawn)  (no BOM)
FID6  Fiducial  [Fiducial10-20]  (value not drawn)  (no BOM)
Logo1  Texas Instruments  [TI_Stacked_Overlay_Small]  (no BOM)
Logo3  FCC disclaimer  [FCC_disclaimer]  (no BOM)
Logo4  WEEE logo  [WEEE_Minimum]  (no BOM)
Logo5  Texas Instruments  [TI_Symbol_Overlay_Small]  (no BOM)
M1  60900213421  [Wurth_60900213421]  (value not drawn)
M2  60900213421  [Wurth_60900213421]  (value not drawn)
M3  60900213421  [Wurth_60900213421]  (value not drawn)
M4  60900213421  [Wurth_60900213421]  (value not drawn)
M5  60900213421  [Wurth_60900213421]  (value not drawn)
M6  60900213421  [Wurth_60900213421]  (value not drawn)
M7  60900213421  [Wurth_60900213421]  (value not drawn)
M8  60900213421  [Wurth_60900213421]  (value not drawn)
M9  60900213421  [Wurth_60900213421]  (value not drawn)
MH1  MTG_NoPads  [NPTH125mil]  (value not drawn)  (no BOM)
MH2  MTG_NoPads  [NPTH125mil]  (value not drawn)  (no BOM)
MH3  MTG_NoPads  [NPTH125mil]  (value not drawn)  (no BOM)
MH4  MTG_NoPads  [NPTH125mil]  (value not drawn)  (no BOM)
ZZ1  These assemblies are ESD sensitive, ESD precautions shall be observed.  [AssemblyNote]  (no BOM)
ZZ2  These assemblies must be clean and free from flux and all contaminants. Use of no clean flux is not acceptable.  [AssemblyNote]  (no BOM)
ZZ3  These assemblies must comply with workmanship standards IPC-A-610 Class 2, unless otherwise specified.  [AssemblyNote]  (no BOM)

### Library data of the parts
!PCB1 = CMP-0003618-2: Manufacturer: Any; PartNumber: MCU089
CE_Logo1 = CMP-0074844-1: SymbolCreator: a0412235
FID1-FID6 = CMP-0077181-1: Fiducial mark.  There is nothing to buy or mount.
Logo1 Logo5 = CMP-0074838-1: Texas Instrument Corporate Signature; SymbolCreator: a0412235; Lib Reference: TI_Logo; Library Reference: Logo
Logo3 = CMP-0074847-1: FCC_disclaimer; Library Reference: Logo
Logo4 = CMP-0074769-1
M1-M9 = CMP-0003761-2: Shunt, 2.54mm, Gold, Black; Manufacturer: Wurth Elektronik
MH1-MH4 = CMP-0078424-2: PCB Mounting Hole, No Pad; Manufacturer: Any; Key: Mounting Hole (non-standard) No Pad
ZZ1 = CMP-0077236-1
ZZ2 = CMP-0077237-1
ZZ3 = CMP-0077238-1

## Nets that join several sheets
+3V3: MCU089B_Connectors (6 pins), MCU089B_AltRouting_Misc (26 pins), MCU089B_F280025C_Device (6 pins), MCU089B_XDS110_USB_Power (21 pins), MCU089B_XDS110_MCU (34 pins)
+5V0: MCU089B_Connectors (10 pins), MCU089B_AltRouting_Misc (C65.2 C67.1 U13.23 U13.24), MCU089B_XDS110_USB_Power (5 pins), MCU089B_XDS110_MCU (R62.1)
GND: MCU089B_Connectors (18 pins), MCU089B_AltRouting_Misc (40 pins), MCU089B_F280025C_Device (42 pins), MCU089B_XDS110_USB_Power (24 pins), MCU089B_XDS110_MCU (37 pins)
VDD: MCU089B_F280025C_Device (9 pins), MCU089B_XDS110_USB_Power (TP1.1)
VDDA: MCU089B_F280025C_Device (C14.2 C15.1 L2.1 U1.26), MCU089B_XDS110_USB_Power (TP3.1)
VDDIO: MCU089B_F280025C_Device (10 pins), MCU089B_XDS110_USB_Power (TP2.1)
ADCINA0/C15: MCU089B_Connectors (J5/J7.69), MCU089B_F280025C_Device (R12.1)
ADCINA1: MCU089B_Connectors (J5/J7.42), MCU089B_F280025C_Device (R13.1)
ADCINA2/C9: MCU089B_Connectors (J1/J3.25), MCU089B_F280025C_Device (R14.1)
ADCINA3/C5: MCU089B_Connectors (J1/J3.24), MCU089B_F280025C_Device (R15.1)
ADCINA4/C14: MCU089B_Connectors (J5/J7.66), MCU089B_F280025C_Device (R16.1)
ADCINA5/C2: MCU089B_Connectors (J5/J7.63), MCU089B_F280025C_Device (R17.1)
ADCINA6: MCU089B_Connectors (J1/J3.23), MCU089B_F280025C_Device (R18.1)
ADCINA7/C3: MCU089B_Connectors (J5/J7.64), MCU089B_F280025C_Device (R19.1)
ADCINA8/C11: MCU089B_Connectors (J5/J7.65), MCU089B_F280025C_Device (R20.1)
ADCINA9/C8: MCU089B_Connectors (J5/J7.67), MCU089B_F280025C_Device (R21.1)
ADCINA10/C10: MCU089B_Connectors (J5/J7.68), MCU089B_F280025C_Device (R22.1)
ADCINA11/C0: MCU089B_Connectors (J1/J3.28), MCU089B_F280025C_Device (R23.1)
ADCINA12/C1: MCU089B_Connectors (J1/J3.29), MCU089B_F280025C_Device (R24.1)
ADCINA14/C4: MCU089B_Connectors (J1/J3.27), MCU089B_F280025C_Device (R25.1)
ADCINA15/C7: MCU089B_Connectors (J1/J3.26), MCU089B_F280025C_Device (R26.1)
ADCINC6: MCU089B_Connectors (J1/J3.2), MCU089B_F280025C_Device (R27.1)
EQEP1A: MCU089B_Connectors (C68.1 J12.1 R72.1), MCU089B_AltRouting_Misc (U13.21)
EQEP1B: MCU089B_Connectors (C69.1 J12.2 R73.1), MCU089B_AltRouting_Misc (U13.20)
EQEP1I: MCU089B_Connectors (C70.1 J12.3 R74.1), MCU089B_AltRouting_Misc (U13.19)
EQEP2A: MCU089B_Connectors (C71.1 J13.1 R75.1), MCU089B_AltRouting_Misc (U13.18)
EQEP2B: MCU089B_Connectors (C72.1 J13.2 R76.1), MCU089B_AltRouting_Misc (U13.17)
EQEP2I: MCU089B_Connectors (C73.1 J13.3 R77.1), MCU089B_AltRouting_Misc (U13.16)
GPIO0: MCU089B_Connectors (J4/J2.40), MCU089B_F280025C_Device (U1.63)
GPIO1: MCU089B_Connectors (J4/J2.39), MCU089B_AltRouting_Misc (R56.2), MCU089B_F280025C_Device (U1.62)
GPIO2: MCU089B_Connectors (J4/J2.38), MCU089B_F280025C_Device (U1.61)
GPIO3: MCU089B_Connectors (J4/J2.37), MCU089B_F280025C_Device (U1.60)
GPIO4: MCU089B_Connectors (J4/J2.36), MCU089B_F280025C_Device (U1.59)
GPIO5: MCU089B_Connectors (J4/J2.19), MCU089B_F280025C_Device (U1.74)
GPIO6_BP: MCU089B_Connectors (J8/J6.78), MCU089B_AltRouting_Misc (R49.2)
GPIO6_FSITXD0: MCU089B_Connectors (J11.6), MCU089B_AltRouting_Misc (R49.1), MCU089B_F280025C_Device (U1.80)
GPIO7_BP: MCU089B_Connectors (J8/J6.77), MCU089B_AltRouting_Misc (R45.2)
GPIO7_FSITXCLK: MCU089B_Connectors (J11.2), MCU089B_AltRouting_Misc (R45.1), MCU089B_F280025C_Device (U1.68)
GPIO8: MCU089B_Connectors (J4/J2.12), MCU089B_AltRouting_Misc (R46.2), MCU089B_F280025C_Device (U1.58)
GPIO9: MCU089B_Connectors (J1/J3.7), MCU089B_F280025C_Device (U1.75)
GPIO10: MCU089B_Connectors (J4/J2.14), MCU089B_AltRouting_Misc (R81.2), MCU089B_F280025C_Device (U1.76)
GPIO11: MCU089B_Connectors (J4/J2.15), MCU089B_F280025C_Device (U1.37)
GPIO12_BP: MCU089B_Connectors (J8/J6.80), MCU089B_AltRouting_Misc (R50.2)
GPIO12_FSIRXD0: MCU089B_Connectors (J11.5), MCU089B_AltRouting_Misc (R50.1 R51.1), MCU089B_F280025C_Device (U1.36)
GPIO13_BP: MCU089B_Connectors (J8/J6.79), MCU089B_AltRouting_Misc (R44.2)
GPIO13_FSIRXCLK: MCU089B_Connectors (J11.1), MCU089B_AltRouting_Misc (R44.1 R46.1), MCU089B_F280025C_Device (U1.35)
GPIO14: MCU089B_AltRouting_Misc (U11.14), MCU089B_F280025C_Device (U1.79)
GPIO14_BP: MCU089B_Connectors (J8/J6.58), MCU089B_AltRouting_Misc (U11.13)
GPIO15: MCU089B_Connectors (J4/J2.35), MCU089B_F280025C_Device (U1.78)
GPIO16: MCU089B_AltRouting_Misc (U8.10), MCU089B_F280025C_Device (U1.39)
GPIO16_BP: MCU089B_Connectors (J8/J6.76), MCU089B_AltRouting_Misc (U8.9)
GPIO17: MCU089B_AltRouting_Misc (U8.6), MCU089B_F280025C_Device (U1.40)
GPIO17_BP: MCU089B_Connectors (J8/J6.75), MCU089B_AltRouting_Misc (U8.7)
GPIO18_BP: MCU089B_Connectors (J4/J2.17), MCU089B_AltRouting_Misc (R36.1)
GPIO18_X2: MCU089B_AltRouting_Misc (R32.1 R36.2), MCU089B_F280025C_Device (U1.50)
GPIO19_BP: MCU089B_Connectors (J4/J2.33), MCU089B_AltRouting_Misc (R37.1)
GPIO19_X1: MCU089B_AltRouting_Misc (R33.1 R37.2), MCU089B_F280025C_Device (U1.51)
GPIO22: MCU089B_Connectors (J5/J7.47), MCU089B_AltRouting_Misc (R42.1), MCU089B_F280025C_Device (U1.67)
GPIO22_PWM_DAC: MCU089B_Connectors (J1/J3.30), MCU089B_AltRouting_Misc (C48.1 R40.2)
GPIO23: MCU089B_Connectors (J4/J2.13), MCU089B_AltRouting_Misc (R43.1), MCU089B_F280025C_Device (U1.65)
GPIO23_PWM_DAC: MCU089B_Connectors (J5/J7.70), MCU089B_AltRouting_Misc (C47.1 R41.2)
GPIO24: MCU089B_Connectors (J5/J7.44 J5/J7.45), MCU089B_AltRouting_Misc (R38.1), MCU089B_F280025C_Device (U1.41)
GPIO25: MCU089B_AltRouting_Misc (U11.15), MCU089B_F280025C_Device (U1.42)
GPIO25_BP: MCU089B_Connectors (J4/J2.31), MCU089B_AltRouting_Misc (U11.1)
GPIO26: MCU089B_AltRouting_Misc (U11.4), MCU089B_F280025C_Device (U1.43)
GPIO26_BP: MCU089B_Connectors (J1/J3.10), MCU089B_AltRouting_Misc (U11.3)
GPIO27: MCU089B_Connectors (J4/J2.11), MCU089B_F280025C_Device (U1.44)
GPIO28: MCU089B_AltRouting_Misc (U6.10), MCU089B_F280025C_Device (U1.4)
GPIO28_BP: MCU089B_Connectors (J1/J3.3), MCU089B_AltRouting_Misc (U6.2)
GPIO29: MCU089B_AltRouting_Misc (U6.6), MCU089B_F280025C_Device (U1.3)
GPIO29_BP: MCU089B_Connectors (J1/J3.4 J1/J3.5), MCU089B_AltRouting_Misc (U6.4)
GPIO30: MCU089B_Connectors (J8/J6.55), MCU089B_F280025C_Device (U1.1)
GPIO31: MCU089B_Connectors (J8/J6.54), MCU089B_AltRouting_Misc (R34.1), MCU089B_F280025C_Device (U1.2)
GPIO32: MCU089B_AltRouting_Misc (R39.2 S4.2), MCU089B_F280025C_Device (U1.49)
GPIO32_BP: MCU089B_Connectors (J8/J6.52), MCU089B_AltRouting_Misc (S4.3)
GPIO32_CANTX: MCU089B_Connectors (TP7.1 U15.1), MCU089B_AltRouting_Misc (S4.1)
GPIO33: MCU089B_AltRouting_Misc (S4.5), MCU089B_F280025C_Device (U1.38)
GPIO33_BP: MCU089B_Connectors (J8/J6.59), MCU089B_AltRouting_Misc (S4.6)
GPIO33_CANRX: MCU089B_Connectors (TP8.1 U15.4), MCU089B_AltRouting_Misc (S4.4)
GPIO34: MCU089B_Connectors (J1/J3.8), MCU089B_AltRouting_Misc (R35.1), MCU089B_F280025C_Device (U1.77)
GPIO35: MCU089B_Connectors (J5/J7.43), MCU089B_F280025C_Device (U1.48)
GPIO37: MCU089B_AltRouting_Misc (U14.15), MCU089B_F280025C_Device (U1.46)
GPIO37_BP: MCU089B_Connectors (J5/J7.49), MCU089B_AltRouting_Misc (U14.1)
GPIO39: MCU089B_Connectors (R69.1 R71.2), MCU089B_F280025C_Device (U1.56)
GPIO40: MCU089B_Connectors (J4/J2.18), MCU089B_F280025C_Device (U1.64)
GPIO41_BP: MCU089B_Connectors (J5/J7.48), MCU089B_AltRouting_Misc (R55.2)
GPIO41_FSIRXD1: MCU089B_Connectors (J11.7), MCU089B_AltRouting_Misc (R55.1 R56.1), MCU089B_F280025C_Device (U1.66)
GPIO42: MCU089B_Connectors (J4/J2.34), MCU089B_F280025C_Device (U1.57)
GPIO43: MCU089B_AltRouting_Misc (U14.4), MCU089B_F280025C_Device (U1.54)
GPIO43_BP: MCU089B_Connectors (J1/J3.9), MCU089B_AltRouting_Misc (U14.3)
GPIO44: MCU089B_AltRouting_Misc (U14.14), MCU089B_F280025C_Device (U1.69)
GPIO44_BP: MCU089B_Connectors (J5/J7.50), MCU089B_AltRouting_Misc (U14.13)
GPIO45: MCU089B_Connectors (J8/J6.74), MCU089B_F280025C_Device (U1.73)
GPIO46_BP: MCU089B_Connectors (J8/J6.51), MCU089B_AltRouting_Misc (R54.2)
GPIO46_FSITXD1: MCU089B_Connectors (J11.8), MCU089B_AltRouting_Misc (R54.1), MCU089B_F280025C_Device (U1.6)
MCU_RXD: MCU089B_AltRouting_Misc (U9.6), MCU089B_XDS110_MCU (J101.2)
MCU_TCK: MCU089B_F280025C_Device (U1.45), MCU089B_XDS110_MCU (J101.8)
MCU_TMS: MCU089B_F280025C_Device (R10.1 U1.47), MCU089B_XDS110_MCU (J101.6)
MCU_TXD: MCU089B_AltRouting_Misc (U9.10), MCU089B_XDS110_MCU (J101.4)
XDS_DM: MCU089B_XDS110_USB_Power (R1.2), MCU089B_XDS110_MCU (U2.93)
XDS_DP: MCU089B_XDS110_USB_Power (R2.2), MCU089B_XDS110_MCU (U2.94)
XRSn: MCU089B_Connectors (J4/J2.16 J8/J6.56), MCU089B_F280025C_Device (C17.2 R11.1 S1.4 U1.5), MCU089B_XDS110_USB_Power (C7.1 R4.1 R5.2)

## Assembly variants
001: not fitted C25 C26 C27 C28 C29 C30 C31 C32 C33 C34 C35 C36 C37 C38 C39 C40 FID1 FID2 FID3 FID4 FID5 FID6 J10 R36 R37 R46 R47 R48 R51 R56 R67 R69 R81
